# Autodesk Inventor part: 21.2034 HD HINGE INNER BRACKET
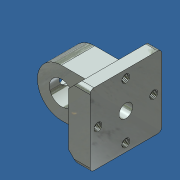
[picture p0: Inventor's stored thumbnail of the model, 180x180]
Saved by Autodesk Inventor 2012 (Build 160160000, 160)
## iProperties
Created: 2014-05
Part Number: 21.2034 HD HINGE INNER BRACKET
Material: Steel
Document SubType Name: Modeling
Designer: Admin
Density: 7.85 g/cm^3
Mass: 287.973 g
Surface Area: 108.653 cm^2
Volume: 36.6845 cm^3
Author: Admin
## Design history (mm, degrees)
node "Product1"
node "Base1"
body "Solid1"
